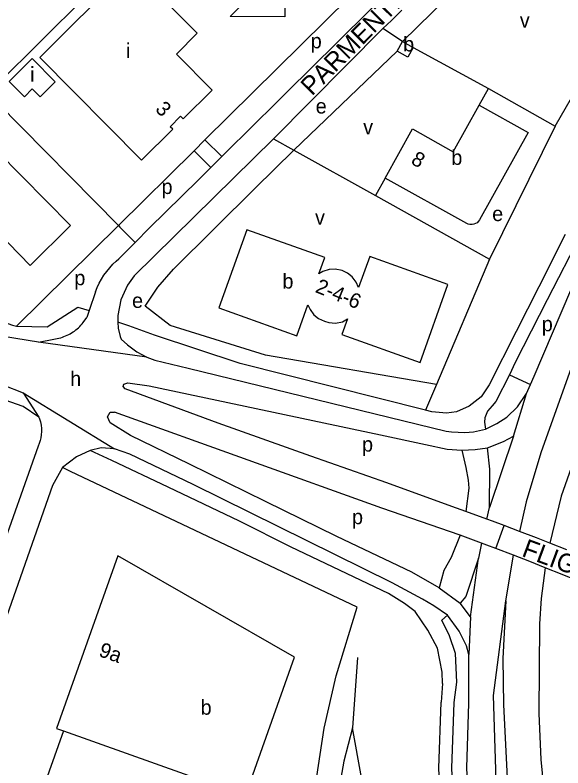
# Model space of a CAD drawing. Extents: x 154765 to 156627, y 383996 to 386132.
# Drawn here: x 155749.2 to 155897.4, y 385032.8 to 385236.2 of the extents above; entities that cross this region are included whole.
import ezdxf

# ---------------------------------------------------------------- set-up
doc = ezdxf.new("R2010")
doc.units = 0
for name, color, linetype in [('BLT_Basislijn', 7, 'Continuous'), ('BLT_Bebouwing', 7, 'Continuous'), ('BLT_Centroide', 7, 'Continuous'), ('BLT_Huisnummer', 7, 'Continuous'), ('BLT_Huisnummer_reeks', 7, 'Continuous'), ('BLT_Onderverdeling_panden', 7, 'Continuous'), ('BLT_Straatnaam', 7, 'Continuous'), ('BLT_Vlakafsluiter', 7, 'Continuous')]:
    doc.layers.add(name, color=color, linetype=linetype)

msp = doc.modelspace()

# ---------------------------------------------------------------- linework, layer by layer
at = {"layer": 'BLT_Basislijn'}
for p, q in [((155853.99, 385229.02), (155918.18, 385292.41)), ((155788.81, 385261.42), (155741.91, 385215.01)), ((155848.75, 385250), (155800.59, 385202.43)), ((155853.77, 385237.45), (155850.97, 385234.72)), ((155853.99, 385229.02), (155848.7, 385232.5)), ((155824.57, 385199.69), (155852.54, 385226.4)), ((155856.89, 385227.42), (155877.23, 385216.33)), ((155874.71, 385211.81), (155877.23, 385216.33)), ((155877.23, 385216.33), (155895.26, 385206.11)), ((155741.91, 385215.01), (155777.19, 385179.31)), ((155895.26, 385206.11), (155877.46, 385170.23)), ((155800.59, 385202.43), (155797.64, 385199.51)), ((155800.59, 385202.43), (155805.18, 385197.99)), ((155819.11, 385202.74), (155824.57, 385199.69)), ((155797.64, 385199.51), (155777.19, 385179.31)), ((155797.64, 385199.51), (155802.17, 385194.97)), ((155824.57, 385199.69), (155846.68, 385187.38)), ((155910.67, 385193.48), (155893.07, 385159.27)), ((155849.33, 385192.14), (155846.68, 385187.38)), ((155846.68, 385187.38), (155877.46, 385170.23)), ((155777.19, 385179.31), (155749.64, 385152.13)), ((155777.19, 385179.31), (155777.61, 385178.88)), ((155777.61, 385178.88), (155781.71, 385174.73)), ((155785.62, 385178.71), (155781.71, 385174.73)), ((155897.99, 385176.89), (155890.81, 385162.78)), ((155781.71, 385174.73), (155777.34, 385170.3)), ((155877.46, 385170.23), (155863.13, 385136.39)), ((155890.81, 385162.78), (155884.74, 385150.7)), ((155771.01, 385161.39), (155769.27, 385156.35)), ((155889.58, 385138.66), (155899.46, 385161.88)), ((155893.07, 385159.27), (155884.45, 385142.33)), ((155769.27, 385156.35), (155768.62, 385154.46)), ((155884.74, 385150.7), (155877.42, 385136.32)), ((155860.17, 385129.4), (155810.11, 385142.06)), ((155884.45, 385142.33), (155882.86, 385139.01)), ((155900.01, 385142.15), (155891.39, 385117.95)), ((155796.05, 385140.82), (155865.75, 385123.72)), ((155882.86, 385139.01), (155879.2, 385131.8)), ((155882.86, 385139.01), (155888.57, 385136.33)), ((155888.57, 385136.33), (155889.58, 385138.66)), ((155778.46, 385135.82), (155778.67, 385136.44)), ((155778.67, 385136.44), (155779.7, 385136.85)), ((155779.7, 385136.85), (155785.49, 385136.03)), ((155785.49, 385136.03), (155848.05, 385122.8)), ((155863.13, 385136.39), (155860.17, 385129.4)), ((155877.42, 385136.32), (155875.29, 385133.01)), ((155887.54, 385133.95), (155888.57, 385136.33)), ((155751.44, 385134.14), (155755.7, 385127.53)), ((155779, 385135.19), (155778.46, 385135.82)), ((155804.11, 385125.95), (155779, 385135.19)), ((155885.03, 385130.34), (155887.54, 385133.95)), ((155875.29, 385133.01), (155872.04, 385130.52)), ((155872.04, 385130.52), (155868.59, 385128.99)), ((155878.25, 385130.65), (155876.99, 385129.17)), ((155879.2, 385131.8), (155878.25, 385130.65)), ((155882.16, 385127.52), (155885.03, 385130.34)), ((155774.21, 385127.67), (155774.93, 385128.88)), ((155774.93, 385128.88), (155776.13, 385128.88)), ((155848.38, 385102.93), (155776.13, 385128.88)), ((155861.89, 385128.99), (155860.17, 385129.4)), ((155865.91, 385128.61), (155861.89, 385128.99)), ((155868.59, 385128.99), (155865.91, 385128.61)), ((155876.99, 385129.17), (155876.25, 385127.39)), ((155774.93, 385125.98), (155774.21, 385127.67)), ((155780.48, 385122.6), (155774.93, 385125.98)), ((155829.22, 385117), (155804.11, 385125.95)), ((155876.25, 385127.39), (155876.15, 385126.23)), ((155876.15, 385126.23), (155876.43, 385124.33)), ((155876.43, 385124.33), (155879.49, 385125.79)), ((155879.49, 385125.79), (155882.16, 385127.52)), ((155873.21, 385123.59), (155876.43, 385124.33)), ((155796.4, 385114.88), (155780.48, 385122.6)), ((155848.05, 385122.8), (155860.23, 385120.12)), ((155865.75, 385123.72), (155867.25, 385123.59)), ((155867.25, 385123.59), (155870.86, 385123.43)), ((155870.86, 385123.43), (155873.21, 385123.59)), ((155883.98, 385122.39), (155877.52, 385103.15)), ((155881.3, 385120.95), (155883.98, 385122.39)), ((155755.51, 385119.74), (155728.73, 385044.96)), ((155860.23, 385120.12), (155866.02, 385118.88)), ((155876.96, 385119.29), (155881.3, 385120.95)), ((155769.51, 385118.52), (155765.89, 385116.83)), ((155772.52, 385119.22), (155769.51, 385118.52)), ((155775.42, 385115.84), (155769.51, 385118.52)), ((155776.14, 385118.98), (155772.52, 385119.22)), ((155780.24, 385117.53), (155776.14, 385118.98)), ((155866.02, 385118.88), (155869.99, 385118.65)), ((155869.99, 385118.65), (155871.13, 385113.91)), ((155765.89, 385116.83), (155762.03, 385113.93)), ((155790.61, 385108.6), (155775.42, 385115.84)), ((155797.37, 385109.33), (155780.24, 385117.53)), ((155849.71, 385109.78), (155829.22, 385117)), ((155762.03, 385113.93), (155759.38, 385109.1)), ((155764.26, 385112.84), (155762.03, 385113.93)), ((155816.91, 385104.74), (155796.4, 385114.88)), ((155867.31, 385103.43), (155849.71, 385109.78)), ((155759.38, 385109.1), (155740.4, 385055.14)), ((155809.91, 385099.43), (155790.61, 385108.6)), ((155851.16, 385082.78), (155797.37, 385109.33)), ((155836.21, 385095.33), (155816.91, 385104.74)), ((155871.09, 385102.07), (155867.31, 385103.43)), ((155869.6, 385095.64), (155848.38, 385102.93)), ((155876.77, 385100.03), (155871.09, 385102.07)), ((155876.77, 385100.03), (155877.52, 385103.15)), ((155823.9, 385092.43), (155809.91, 385099.43)), ((155878.29, 385099.49), (155876.77, 385100.03)), ((155881.44, 385098.28), (155878.29, 385099.49)), ((155885.6, 385096.67), (155881.44, 385098.28)), ((155856.47, 385085.67), (155836.21, 385095.33)), ((155873.2, 385094.33), (155869.6, 385095.64)), ((155890.16, 385094.91), (155885.6, 385096.67)), ((155875.38, 385093.51), (155873.2, 385094.33)), ((155875.38, 385093.51), (155874.54, 385089.43)), ((155876.74, 385093), (155875.38, 385093.51)), ((155893.77, 385093.52), (155890.16, 385094.91)), ((155898.37, 385091.75), (155893.77, 385093.52)), ((155850.2, 385079.88), (155823.9, 385092.43)), ((155879.25, 385092.06), (155876.74, 385093)), ((155884.02, 385090.27), (155879.25, 385092.06)), ((155874.54, 385089.43), (155871.13, 385079.14)), ((155872.39, 385073.61), (155874.54, 385089.43)), ((155881.91, 385077.92), (155884.02, 385090.27)), ((155888.41, 385088.52), (155884.02, 385090.27)), ((155892.58, 385086.86), (155888.41, 385088.52)), ((155863.89, 385081.42), (155856.47, 385085.67)), ((155865.12, 385086.12), (155863.89, 385081.42)), ((155897.1, 385085.07), (155892.58, 385086.86)), ((155899.57, 385084.09), (155897.1, 385085.07)), ((155854.54, 385077.23), (155850.2, 385079.88)), ((155871.13, 385079.14), (155869.58, 385077.27)), ((155857.43, 385075.05), (155854.54, 385077.23)), ((155872.39, 385073.61), (155869.58, 385077.27)), ((155860.81, 385069.98), (155857.43, 385075.05)), ((155866.19, 385074.07), (155862.45, 385076.58)), ((155863.47, 385065.16), (155860.81, 385069.98)), ((155864.67, 385058.64), (155863.47, 385065.16)), ((155841.86, 385062.64), (155840.44, 385043.65)), ((155864.75, 385055.62), (155864.67, 385058.64)), ((155864.75, 385055.62), (155864.43, 385050.58))]:
    msp.add_line(p, q, dxfattribs=at)
for points in [[(155895.26, 385206.11), (155915.21, 385240.91), (155925.88, 385257.56), (155936.99, 385273.7)], [(155805.18, 385197.99), (155806.26, 385199.07), (155820.08, 385212.74), (155822.76, 385215.43), (155836.2, 385228.68), (155854.62, 385246.9)], [(155850.97, 385234.72), (155848.7, 385232.5)], [(155848.7, 385232.5), (155819.11, 385202.74)], [(155558.69, 385204.04), (155671.59, 385164), (155719.27, 385147.11), (155745.95, 385136.27), (155751.44, 385134.14)], [(155819.11, 385202.74), (155781.45, 385165.72), (155779.6, 385163.19), (155777.8, 385159.24), (155777.01, 385154.98), (155777.04, 385153.17)], [(155863.13, 385136.39), (155816.94, 385144.28), (155791.16, 385152.34), (155784.39, 385157.57), (155787.84, 385162.69), (155792.09, 385167.56), (155814.13, 385189.36), (155824.57, 385199.69)], [(155802.17, 385194.97), (155802.83, 385195.63), (155805.18, 385197.99)], [(155802.17, 385194.97), (155798.76, 385191.56), (155785.62, 385178.71)], [(155755.57, 385147.79), (155746.1, 385149.29), (155734.81, 385152.01), (155728.35, 385154.34), (155704.53, 385162.79), (155673.76, 385173.72)], [(155771.01, 385161.39), (155771.47, 385162.57), (155772.01, 385163.72), (155772.61, 385164.83), (155773.29, 385165.9), (155774.03, 385166.92), (155774.84, 385167.9), (155775.7, 385168.83), (155776.62, 385169.69), (155777.34, 385170.3)], [(155706.21, 385167.51), (155730.03, 385159.05), (155748.54, 385152.39), (155749.64, 385152.13)], [(155749.64, 385152.13), (155757.94, 385151.93), (155766.26, 385157.23), (155769.27, 385156.35)], [(155763.75, 385149.87), (155764.15, 385150.08), (155764.55, 385150.3), (155764.94, 385150.55), (155765.32, 385150.81), (155765.69, 385151.09), (155766.05, 385151.38), (155766.4, 385151.7), (155766.74, 385152.03), (155767.06, 385152.37), (155767.36, 385152.73), (155767.65, 385153.1), (155768.62, 385154.46)], [(155779.97, 385152.17), (155777.04, 385153.17)], [(155777.04, 385153.17), (155777.13, 385151.56), (155777.62, 385149.33), (155777.96, 385148.63), (155779.61, 385147.11)], [(155810.11, 385142.06), (155786.96, 385149.73), (155779.97, 385152.17)], [(155755.57, 385147.79), (155759.71, 385148.59), (155760.66, 385148.75), (155761.12, 385148.86), (155761.58, 385148.99), (155762.03, 385149.13), (155762.47, 385149.29), (155762.91, 385149.47), (155763.34, 385149.66), (155763.75, 385149.87)], [(155779.61, 385147.11), (155779.68, 385147.04), (155782.21, 385145.21), (155784.89, 385143.74)], [(155784.89, 385143.74), (155787.07, 385142.94), (155796.05, 385140.82)], [(155755.7, 385127.53), (155751.4, 385130.42), (155738.57, 385134.96)], [(155755.7, 385127.53), (155755.85, 385127.11), (155756.11, 385126.26), (155756.29, 385125.39), (155756.39, 385124.52), (155756.41, 385123.66), (155756.35, 385122.81), (155756.23, 385121.99), (155756.04, 385121.2), (155755.8, 385120.45), (155755.51, 385119.74)], [(155903.8, 385125.22), (155900.13, 385115.42), (155896.89, 385106.17), (155893.77, 385093.52)], [(155877.52, 385103.15), (155877.6, 385113.46), (155876.96, 385119.29)], [(155891.39, 385117.95), (155887.45, 385104.66), (155885.6, 385096.67)], [(155871.13, 385113.91), (155871.7, 385110.53), (155871.89, 385108.37), (155871.09, 385102.07)], [(155827.56, 384992.1), (155828.67, 385016.24), (155832.77, 385043.5), (155836.07, 385057.7), (155841.73, 385076.19), (155764.26, 385112.84)], [(155869.6, 385095.64), (155867.15, 385089.62), (155865.12, 385086.12)], [(155892.58, 385086.86), (155891.45, 385078.57), (155891.02, 385071.73), (155890.79, 385047.47), (155891.38, 385035.08), (155892.56, 385023.09), (155894.14, 385013.39), (155896.21, 385004.48)], [(155862.45, 385076.58), (155859.42, 385078.41), (155851.16, 385082.78)], [(155962.52, 384826.27), (155935.77, 384871.91), (155901.3, 384935.31), (155901.3, 384935.31), (155894.58, 384950.8), (155887.34, 384971.47), (155883.48, 384986.96), (155879.92, 385009.42), (155878.55, 385052.4), (155881.91, 385077.92)], [(155881.91, 385077.92), (155881.11, 385062.39), (155881.31, 385049.86), (155882.44, 385026.52), (155885.1, 385009.65), (155885.1, 385009.65), (155888.56, 384996.23), (155896.24, 384972.11), (155908.62, 384940.24), (155908.62, 384940.24), (155928.62, 384898.94), (155951.25, 384859.63), (155970.21, 384827.91), (155980.73, 384813.62), (155980.73, 384813.62)], [(155866.19, 385074.07), (155864.61, 385072.69)], [(155871.92, 385063.41), (155871.31, 385065.77), (155869.3, 385069.72), (155866.19, 385074.07)], [(155868.3, 385063.69), (155866.73, 385068.49), (155866.73, 385068.49), (155864.61, 385072.69)], [(155867.93, 385050.46), (155868.66, 385055.95), (155868.3, 385063.69), (155868.3, 385063.69)], [(155871.93, 385050.32), (155871.92, 385063.41)], [(155982.74, 384747.99), (155981.79, 384761.81), (155978.09, 384773), (155961.45, 384799.64), (155934.97, 384845.54), (155909.95, 384888.82), (155891.81, 384922.17), (155885.25, 384935.64), (155874.71, 384962.88), (155867.9, 384989.38), (155864.81, 385012.56), (155863.83, 385032.74), (155864.43, 385050.58)], [(155965.34, 384800.02), (155964.45, 384801.44), (155938, 384847.29), (155913, 384890.54), (155894.92, 384923.78), (155888.46, 384937.04), (155878.05, 384963.95), (155871.35, 384990.05), (155868.3, 385012.88), (155867.33, 385032.77), (155867.93, 385050.46)], [(155968.54, 384801.65), (155941.46, 384849.29), (155916.49, 384892.49), (155898.47, 384925.61), (155892.13, 384938.64), (155881.86, 384965.17), (155875.28, 384990.81), (155872.29, 385013.24), (155871.33, 385032.8), (155871.93, 385050.32)]]:
    msp.add_lwpolyline(points, dxfattribs=at)
msp.add_lwpolyline([(155840.44, 385043.65), (155838.09, 385034.59), (155836.86, 385027.54), (155836.08, 385021.6), (155835.43, 385005.08), (155834.83, 384995.23), (155841.38, 384978.78), (155857.63, 384984), (155858.17, 384985.25), (155842.94, 385030.24)], close=True, dxfattribs=at)
at = {"layer": 'BLT_Bebouwing'}
for p, q in [((155727.29, 385216.68), (155764.2, 385179.29)), ((155740.13, 385181.99), (155753.34, 385168.55)), ((155764.2, 385179.29), (155753.34, 385168.55))]:
    msp.add_line(p, q, dxfattribs=at)
for points in [[(155844.92, 385278.36), (155842.07, 385275.52), (155849.65, 385267.82), (155838.59, 385256.88), (155839.4, 385256), (155822.17, 385238.88), (155822.14, 385235.68), (155807.37, 385235.76), (155810.81, 385239.18), (155800.11, 385250), (155788.81, 385261.42)], [(155794.71, 385208.1), (155802.53, 385215.87), (155792.86, 385225.63), (155798.48, 385231.29), (155794.94, 385234.81), (155780.67, 385249.27), (155762.86, 385231.59)], [(155762.86, 385231.59), (155755.91, 385224.69), (155783.47, 385196.93), (155791.89, 385205.29)], [(155852.54, 385226.4), (155853.99, 385229.02)], [(155853.99, 385229.02), (155856.89, 385227.42)], [(155856.89, 385227.42), (155855.43, 385224.78), (155852.54, 385226.4)], [(155849.33, 385192.14), (155856.7, 385205.4), (155867.71, 385199.24), (155874.71, 385211.81)], [(155874.71, 385211.81), (155887.94, 385204.45)], [(155791.89, 385205.29), (155791.21, 385205.99), (155794.01, 385208.81), (155794.71, 385208.1)], [(155887.94, 385204.45), (155874.76, 385180.8), (155874.51, 385180.44), (155874.12, 385180.07), (155873.69, 385179.82), (155873.26, 385179.65), (155872.77, 385179.56), (155872.21, 385179.57), (155871.74, 385179.67), (155871.38, 385179.85), (155849.33, 385192.14)], [(155831.39, 385166.25), (155832.96, 385170.63), (155811.86, 385178.15), (155804.33, 385157.05), (155825.43, 385149.52), (155828.42, 385157.92)], [(155839.13, 385154.09), (155837.62, 385149.85), (155858.72, 385142.33), (155866.24, 385163.42), (155845.15, 385170.93), (155842.12, 385162.58)], [(155842.12, 385162.58), (155841.49, 385164.04), (155840.38, 385165.48), (155839.11, 385166.48), (155837.69, 385167.15), (155835.78, 385167.52), (155834.14, 385167.41), (155832.48, 385166.88), (155831.39, 385166.25)], [(155828.42, 385157.92), (155829.04, 385156.61), (155830.05, 385155.19), (155831.3, 385154.16), (155832.87, 385153.46), (155834.05, 385153.08), (155835.88, 385152.97), (155837.74, 385153.33), (155839.13, 385154.09)], [(155777.02, 385090.13), (155760.49, 385043.48), (155762.36, 385042.82)], [(155809.65, 385026.03), (155811.53, 385025.36), (155824.79, 385062.76), (155777.02, 385090.13)], [(155762.36, 385042.82), (155753.18, 385017), (155751.43, 385017.62), (155744.64, 384998.23), (155746.3, 384997.64), (155740.17, 384980.4), (155738.59, 384980.96), (155696.77, 384862.93)]]:
    msp.add_lwpolyline(points, dxfattribs=at)
msp.add_lwpolyline([(155753.85, 385224.43), (155747.62, 385218.24), (155751.76, 385214.07), (155753.9, 385216.2), (155756.03, 385214.06), (155760.12, 385218.12)], close=True, dxfattribs=at)
at = {"layer": 'BLT_Onderverdeling_panden'}
msp.add_line((155762.36, 385042.82), (155809.65, 385026.03), dxfattribs=at)
at = {"layer": 'BLT_Vlakafsluiter'}
for p, q in [((155784.89, 385143.74), (155755.57, 385147.79)), ((155751.44, 385134.14), (155776.14, 385118.98)), ((155883.98, 385122.39), (155887.54, 385133.95)), ((155879.25, 385092.06), (155881.44, 385098.28)), ((155863.89, 385081.42), (155869.58, 385077.27)), ((155872.39, 385073.61), (155871.92, 385063.41))]:
    msp.add_line(p, q, dxfattribs=at)
msp.add_lwpolyline([(155869.99, 385118.65), (155873.65, 385118.8), (155876.96, 385119.29)], dxfattribs=at)

# ---------------------------------------------------------------- texts
at = {"layer": 'BLT_Centroide'}
for s, p in [('v', (155885.7, 385232.75)), ('p', (155829.18, 385227.17)), ('b', (155854.16, 385226.33)), ('i', (155779.22, 385224.53)), ('i', (155753.32, 385218.14)), ('e', (155830.52, 385209.56)), ('v', (155843.36, 385203.94)), ('b', (155867.18, 385195.69)), ('p', (155788.84, 385187.82)), ('e', (155878.23, 385180.5)), ('v', (155830.34, 385179.54)), ('b', (155821.53, 385162.29)), ('p', (155765.28, 385163.18)), ('e', (155780.88, 385157.05)), ('p', (155891.63, 385150.74)), ('h', (155764.15, 385135.92)), ('p', (155843.05, 385118.24)), ('p', (155840.34, 385098.63)), ('b', (155799.4, 385047.17))]:
    msp.add_text(s, height=4, dxfattribs=at).set_placement(p)
at = {"layer": 'BLT_Huisnummer'}
for s, rotation, p in [('3', 314.6587, (155786.92, 385210.52)), ('8', 330.8188, (155856.01, 385196.14)), ('9a', 340.6859, (155771.63, 385063.07))]:
    msp.add_text(s, height=4, rotation=rotation, dxfattribs=at).set_placement(p)
at = {"layer": 'BLT_Huisnummer_reeks'}
msp.add_text('2-4-6', height=4, rotation=337.7847, dxfattribs=at).set_placement((155830.17, 385161.39))
at = {"layer": 'BLT_Straatnaam'}
for s, rotation, p in [('PARMENTIERWEG', 45.2581, (155829.49, 385214.12)), ('FLIGHT LANE', 339.6933, (155885.96, 385090.09))]:
    msp.add_text(s, height=5, rotation=rotation, dxfattribs=at).set_placement(p)

doc.saveas('drawing.dxf')
